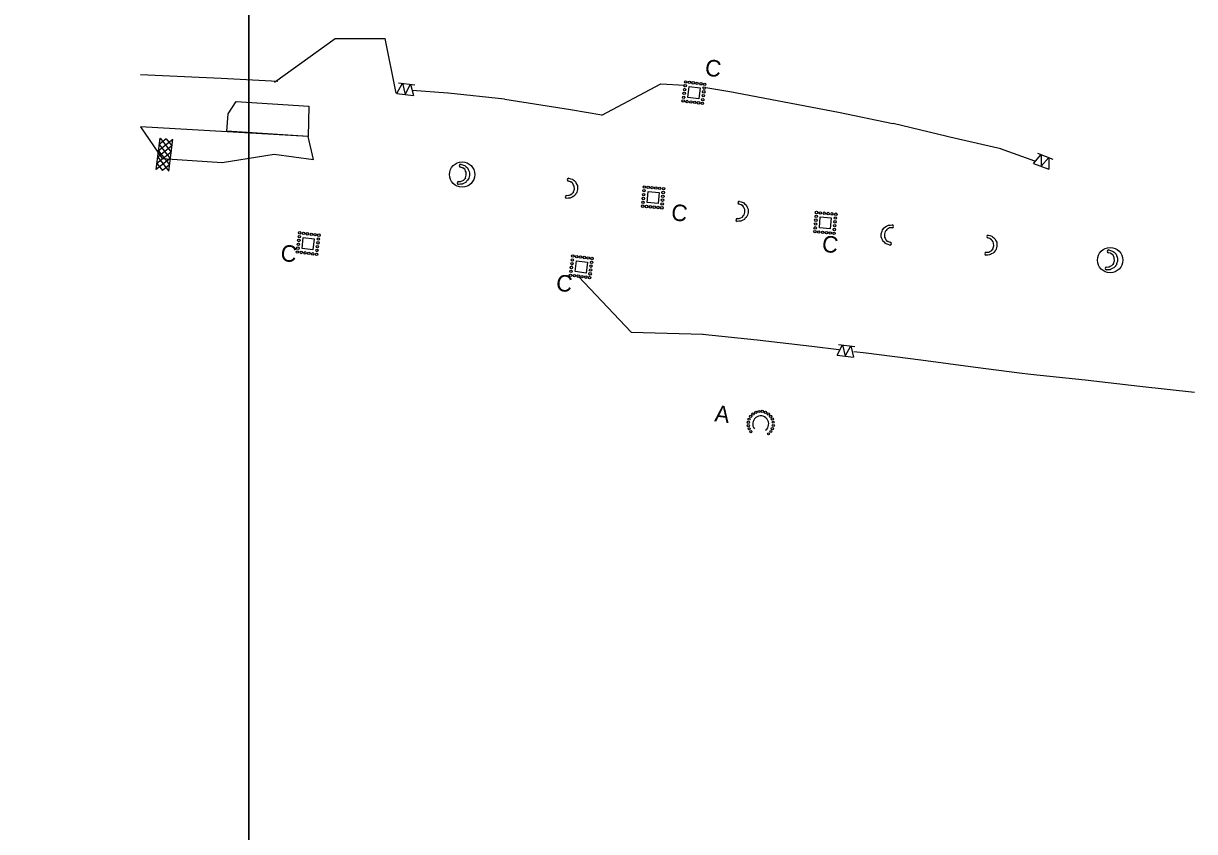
# Model space of a CAD drawing. Extents: x 2470000 to 2520000, y 340000 to 380000.
# Drawn here: x 2479795 to 2480859, y 365742 to 366476 of the extents above; entities that cross this region are included whole.
import ezdxf

# ---------------------------------------------------------------- set-up
doc = ezdxf.new("R2010")
doc.units = 0
for name, color, linetype in [('Bare Soil (Coastal) Drainage Area Border FG Drainage', 7, 'Continuous'), ('Coir Fiber Wattle with PAM Both CELL', 7, 'Continuous'), ('Coir Fiber Wattle with PAM CG CELL', 7, 'Continuous'), ('Label A Both CELL', 7, 'Continuous'), ('Prop Guardrail Anchor Unit CELL', 7, 'Continuous'), ('Prop Structure Anchor Unit CELL', 7, 'Continuous'), ('Rock Pipe Inlet Sediment Trap Type A Both CELL', 7, 'Continuous'), ('Rock Silt Check Type A Both CELL', 7, 'Continuous'), ('Scratch_Level_6', 7, 'Continuous'), ('Sheet Data Field CELL', 7, 'Continuous'), ('Special Sediment Control Fence Section Both CELL', 7, 'Continuous'), ('Wattle Both CELL', 7, 'Continuous'), ('Wattle CG CELL', 7, 'Continuous'), ('Wattle Final CELL', 7, 'Continuous')]:
    doc.layers.add(name, color=color, linetype=linetype)

# ---------------------------------------------------------------- blocks, each defined once
blk = doc.blocks.new('C2')
at = {"layer": 'Prop Guardrail Anchor Unit CELL'}
blk.add_text('C', height=0.3, dxfattribs=at).set_placement((-0.161, -0.136))
blk = doc.blocks.new('A2')
at = {"layer": 'Label A Both CELL'}
blk.add_text('A', height=0.3, dxfattribs=at).set_placement((-0.133, -0.151))

msp = doc.modelspace()

# ---------------------------------------------------------------- linework, layer by layer
at = {"layer": 'Bare Soil (Coastal) Drainage Area Border FG Drainage'}
for points in [[(2479981.3, 366393.9), (2479988.7, 366404.9), (2480054.6, 366400.8), (2480054, 366373.2), (2479980, 366378)], [(2479901.7, 366382), (2479921.4, 366353.2), (2479976, 366349.6), (2480023, 366357.3), (2480058.9, 366352.5), (2480054, 366373.2)]]:
    msp.add_lwpolyline(points, close=True, dxfattribs=at)
at = {"layer": 'Coir Fiber Wattle with PAM Both CELL'}
for p, q in [((2480194.1, 366344.9), (2480192.4, 366345.4)), ((2480194.1, 366344.9), (2480194.5, 366344.8)), ((2480195.6, 366343.8), (2480194.5, 366344.8)), ((2480196.4, 366343.2), (2480195.6, 366343.8)), ((2480197, 366341.9), (2480196.4, 366343.2)), ((2480196.8, 366335.7), (2480197.6, 366338.2)), ((2480197.5, 366340.8), (2480197, 366341.9)), ((2480197.6, 366338.2), (2480197.5, 366340.8)), ((2480197.6, 366338.2), (2480197.6, 366338.2)), ((2480190.6, 366332.5), (2480192.2, 366332.5)), ((2480192.2, 366332.5), (2480193, 366332.6)), ((2480193, 366332.6), (2480193.9, 366333.1)), ((2480193.9, 366333.1), (2480195.2, 366333.7)), ((2480195.4, 366333.9), (2480195.2, 366333.7)), ((2480195.4, 366333.9), (2480196.1, 366334.8)), ((2480196.8, 366335.7), (2480196.1, 366334.8))]:
    msp.add_line(p, q, dxfattribs=at)
msp.add_lwpolyline([(2480192.7, 366348), (2480194.2, 366347.6), (2480195.9, 366347), (2480196.6, 366346.5), (2480197.3, 366345.9), (2480198.7, 366344.7), (2480198.7, 366344.7), (2480198.9, 366344.3), (2480199, 366344.2), (2480199.4, 366343.4), (2480199.7, 366342.8), (2480200.3, 366341.5), (2480200.4, 366340.4), (2480200.6, 366337.9), (2480200.6, 366337.9), (2480199.8, 366335.3), (2480199.4, 366334.4), (2480198.7, 366333.5), (2480198.5, 366333.3), (2480197.9, 366332.6), (2480197.5, 366332), (2480197.3, 366331.9), (2480197.1, 366331.6), (2480197.1, 366331.6), (2480195.7, 366331), (2480194.5, 366330.4), (2480193.8, 366330), (2480192, 366329.9), (2480190.5, 366329.8)], dxfattribs=at)
msp.add_circle((2480193.8, 366338.7), 11.5, dxfattribs=at)
for centre, radius, start in [((2480192.5, 366346.7), 1.3, 83.0023), ((2480190.7, 366331.1), 1.33, 91.8897)]:
    msp.add_arc(centre, radius, start, 263.0023, dxfattribs=at)
at = {"layer": 'Coir Fiber Wattle with PAM CG CELL'}
for p, q in [((2480782.5, 366267.2), (2480780.8, 366267.7)), ((2480782.5, 366267.2), (2480782.8, 366267.1)), ((2480784, 366266.1), (2480782.8, 366267.1)), ((2480784.8, 366265.5), (2480784, 366266.1)), ((2480785.4, 366264.1), (2480784.8, 366265.5)), ((2480785.9, 366263.1), (2480785.4, 366264.1)), ((2480786, 366260.5), (2480785.9, 366263.1)), ((2480779, 366254.7), (2480780.6, 366254.8)), ((2480780.6, 366254.8), (2480781.3, 366254.9)), ((2480781.3, 366254.9), (2480782.3, 366255.4)), ((2480782.3, 366255.4), (2480783.6, 366256)), ((2480783.8, 366256.2), (2480783.6, 366256)), ((2480783.8, 366256.2), (2480784.5, 366257.1)), ((2480785.2, 366258), (2480784.5, 366257.1)), ((2480785.2, 366258), (2480786, 366260.5)), ((2480786, 366260.5), (2480786, 366260.5))]:
    msp.add_line(p, q, dxfattribs=at)
msp.add_lwpolyline([(2480781.1, 366270.3), (2480782.6, 366269.9), (2480784.3, 366269.3), (2480784.9, 366268.8), (2480785.7, 366268.2), (2480787.1, 366267), (2480787.1, 366267), (2480787.3, 366266.6), (2480787.4, 366266.5), (2480787.8, 366265.7), (2480788.1, 366265.1), (2480788.7, 366263.7), (2480788.8, 366262.7), (2480788.9, 366260.2), (2480788.9, 366260.1), (2480788.1, 366257.6), (2480787.8, 366256.7), (2480787.1, 366255.8), (2480786.9, 366255.6), (2480786.3, 366254.9), (2480785.8, 366254.3), (2480785.7, 366254.2), (2480785.5, 366253.9), (2480785.5, 366253.9), (2480784.1, 366253.3), (2480782.9, 366252.7), (2480782.2, 366252.3), (2480780.4, 366252.2), (2480778.9, 366252.1)], dxfattribs=at)
msp.add_circle((2480782.2, 366261), 11.5, dxfattribs=at)
for centre, radius, start in [((2480780.9, 366269), 1.3, 83.0023), ((2480779, 366253.4), 1.33, 91.8897)]:
    msp.add_arc(centre, radius, start, 263.0023, dxfattribs=at)
at = {"layer": 'Prop Structure Anchor Unit CELL'}
for points in [[(2480400, 366418.6), (2480409.9, 366417.4), (2480408.7, 366407.5), (2480398.7, 366408.7)], [(2480362.6, 366323.4), (2480372.6, 366322.5), (2480371.7, 366312.5), (2480361.8, 366313.4)], [(2480519, 366300.2), (2480529, 366299.3), (2480528.1, 366289.3), (2480518.2, 366290.2)], [(2480049.6, 366281.6), (2480059.5, 366280.4), (2480058.3, 366270.5), (2480048.4, 366271.7)], [(2480297.6, 366260.5), (2480307.5, 366259.3), (2480306.3, 366249.3), (2480296.4, 366250.6)]]:
    msp.add_lwpolyline(points, close=True, dxfattribs=at)
for centre in [(2480396.7, 366422.8), (2480400.2, 366422.4), (2480403.6, 366422), (2480407.1, 366421.6), (2480395.4, 366412.4), (2480395.8, 366415.9), (2480396.3, 366419.4), (2480410.6, 366421.1), (2480413.2, 366413.8), (2480413.6, 366417.2), (2480414.1, 366420.7), (2480394.5, 366405.5), (2480395, 366408.9), (2480398, 366405), (2480401.5, 366404.6), (2480405, 366404.2), (2480408.4, 366403.8), (2480411.9, 366403.3), (2480412.3, 366406.8), (2480412.8, 366410.3), (2480359.2, 366327.4), (2480362.7, 366327.1), (2480366.2, 366326.8), (2480369.7, 366326.5), (2480373.2, 366326.2), (2480376.7, 366325.9), (2480358.3, 366317), (2480358.6, 366320.5), (2480358.9, 366324), (2480375.7, 366315.5), (2480376, 366318.9), (2480376.3, 366322.4), (2480357.7, 366310), (2480358, 366313.5), (2480361.2, 366309.7), (2480364.7, 366309.4), (2480368.2, 366309.1), (2480371.6, 366308.8), (2480375.1, 366308.5), (2480375.4, 366312), (2480514.7, 366293.8), (2480515, 366297.3), (2480515.3, 366300.8), (2480515.6, 366304.3), (2480519.1, 366303.9), (2480522.6, 366303.6), (2480526.1, 366303.3), (2480529.6, 366303), (2480532.4, 366295.8), (2480532.7, 366299.2), (2480533.1, 366302.7), (2480046.3, 366285.8), (2480049.8, 366285.4), (2480053.3, 366284.9), (2480056.8, 366284.5), (2480060.2, 366284.1), (2480063.7, 366283.7), (2480514.1, 366286.8), (2480514.4, 366290.3), (2480517.6, 366286.5), (2480521.1, 366286.2), (2480524.6, 366285.9), (2480528, 366285.6), (2480531.5, 366285.3), (2480531.8, 366288.8), (2480532.1, 366292.3), (2480045.1, 366275.4), (2480045.5, 366278.9), (2480045.9, 366282.3), (2480062.4, 366273.2), (2480062.9, 366276.7), (2480063.3, 366280.2), (2480044.2, 366268.4), (2480044.6, 366271.9), (2480047.7, 366268), (2480051.2, 366267.6), (2480054.6, 366267.2), (2480058.1, 366266.7), (2480061.6, 366266.3), (2480062, 366269.8), (2480294.3, 366264.7), (2480297.8, 366264.2), (2480301.3, 366263.8), (2480304.7, 366263.4), (2480308.2, 366263), (2480311.7, 366262.5), (2480293, 366254.3), (2480293.5, 366257.7), (2480293.9, 366261.2), (2480310.4, 366252.1), (2480310.8, 366255.6), (2480311.3, 366259.1), (2480292.2, 366247.3), (2480292.6, 366250.8), (2480295.7, 366246.9), (2480299.1, 366246.5), (2480302.6, 366246), (2480306.1, 366245.6), (2480309.5, 366245.2), (2480310, 366248.6)]:
    msp.add_circle(centre, 1.12, dxfattribs=at)
at = {"layer": 'Rock Pipe Inlet Sediment Trap Type A Both CELL'}
for centre in [(2480453.6, 366113.7), (2480454.3, 366116.6), (2480455.8, 366119.2), (2480457.9, 366121.3), (2480460.5, 366122.8), (2480463.3, 366123.6), (2480466.3, 366123.7), (2480469.2, 366122.9), (2480471.8, 366121.4), (2480473.9, 366119.3), (2480475.4, 366116.8), (2480476.2, 366113.9), (2480453.6, 366110.7), (2480454.4, 366107.9), (2480455.9, 366105.3), (2480472, 366103.3), (2480474.1, 366105.4), (2480475.5, 366108), (2480476.3, 366110.9)]:
    msp.add_circle(centre, 1.01, dxfattribs=at)
msp.add_arc((2480464.9, 366112.3), 7.26, 308.0018, 217.9929, dxfattribs=at)
at = {"layer": 'Rock Silt Check Type A Both CELL'}
for p, q in [((2479916, 366343.2), (2479919.5, 366371.9)), ((2479931, 366370.5), (2479918.1, 366360.4)), ((2479925.2, 366371.2), (2479918.8, 366366.1)), ((2479919.5, 366371.9), (2479929.5, 366359)), ((2479925.2, 366371.2), (2479930.3, 366364.7)), ((2479927.4, 366341.8), (2479931, 366370.5)), ((2479929.5, 366359), (2479916.7, 366348.9)), ((2479930.3, 366364.7), (2479917.4, 366354.6)), ((2479918.1, 366360.4), (2479928.1, 366347.5)), ((2479918.8, 366366.1), (2479928.8, 366353.2)), ((2479928.8, 366353.2), (2479916, 366343.2)), ((2479916.7, 366348.8), (2479921.7, 366342.5)), ((2479917.4, 366354.6), (2479927.4, 366341.8)), ((2479928.1, 366347.5), (2479921.7, 366342.5))]:
    msp.add_line(p, q, dxfattribs=at)
at = {"layer": 'Scratch_Level_6'}
for points in [[(2470000, 360000), (2480000, 360000), (2480000, 370000), (2470000, 370000)], [(2480000, 360000), (2490000, 360000), (2490000, 370000), (2480000, 370000)]]:
    msp.add_lwpolyline(points, close=True, dxfattribs=at)
at = {"layer": 'Sheet Data Field CELL'}
for p, q in [((2480023.3, 366422.5), (2480078.6, 366462.3)), ((2480078.6, 366462.3), (2480124, 366462.2)), ((2480134, 366412.7), (2480124, 366462.2)), ((2479901.8, 366429.7), (2479975, 366426.3)), ((2479975, 366426.3), (2480026.5, 366423.4)), ((2480180.9, 366412.5), (2480148.5, 366415.1)), ((2480232.3, 366407.1), (2480181, 366412.5)), ((2480320.6, 366392.7), (2480374.1, 366421.1)), ((2480374.1, 366421.1), (2480395.6, 366419.9)), ((2480415, 366417.7), (2480436.9, 366414.2)), ((2480436.9, 366414.2), (2480486.2, 366404.8)), ((2480292.1, 366397.4), (2480232.6, 366407)), ((2480486.2, 366404.8), (2480535.4, 366395.3)), ((2480320.6, 366392.7), (2480292.1, 366397.4)), ((2480535.6, 366395.3), (2480584.8, 366385.1)), ((2480634.1, 366373.3), (2480585.1, 366385.1)), ((2480683, 366362), (2480634, 366373.3)), ((2480713.7, 366351), (2480682.7, 366362.1)), ((2480299.4, 366246.1), (2480347.4, 366195.7)), ((2480347.4, 366195.7), (2480412.7, 366193.7)), ((2480411.9, 366193.8), (2480461.7, 366188.6)), ((2480461.6, 366188.6), (2480511.2, 366182.8)), ((2480511.2, 366182.8), (2480535.8, 366179.8)), ((2480549.6, 366178.1), (2480560.8, 366176.8)), ((2480560.7, 366176.8), (2480610.3, 366170.4)), ((2480610.3, 366170.4), (2480659.9, 366163.9)), ((2480659.9, 366163.9), (2480699.9, 366158.7)), ((2480700, 366158.7), (2480709.8, 366157.6)), ((2480709.8, 366157.6), (2480759.4, 366152.2)), ((2480759.4, 366152.2), (2480809.1, 366146.7)), ((2480809.1, 366146.7), (2480858.8, 366141.2))]:
    msp.add_line(p, q, dxfattribs=at)
at = {"layer": 'Special Sediment Control Fence Section Both CELL'}
for p, q in [((2480134.6, 366412.2), (2480149.5, 366410.4)), ((2480135.9, 366422.1), (2480150.7, 366420.3)), ((2480712.5, 366348.8), (2480726.6, 366343.5)), ((2480716.1, 366358.2), (2480730.1, 366352.8)), ((2480535.4, 366184.5), (2480550.3, 366182.7)), ((2480534.2, 366174.6), (2480549.1, 366172.8))]:
    msp.add_line(p, q, dxfattribs=at)
for points in [[(2480134.6, 366412.2), (2480139.6, 366421.7), (2480142.1, 366411.3)], [(2480142.1, 366411.3), (2480147, 366420.7), (2480149.5, 366410.4)], [(2480712.5, 366348.8), (2480719.6, 366356.8), (2480719.6, 366346.2)], [(2480719.6, 366346.2), (2480726.6, 366354.2), (2480726.6, 366343.5)], [(2480534.2, 366174.6), (2480539.1, 366184.1), (2480541.6, 366173.7)], [(2480541.6, 366173.7), (2480546.6, 366183.1), (2480549.1, 366172.8)]]:
    msp.add_lwpolyline(points, dxfattribs=at)
at = {"layer": 'Wattle Both CELL'}
for p, q in [((2480292.2, 366332.2), (2480290.4, 366332.8)), ((2480292.2, 366332.2), (2480292.5, 366332.1)), ((2480293.6, 366331.2), (2480292.5, 366332.1)), ((2480294.4, 366330.5), (2480293.6, 366331.2)), ((2480295, 366329.2), (2480294.4, 366330.5)), ((2480295.5, 366328.1), (2480295, 366329.2)), ((2480295.7, 366325.6), (2480295.5, 366328.1)), ((2480288.7, 366319.8), (2480290.3, 366319.9)), ((2480290.3, 366319.9), (2480291.1, 366319.9)), ((2480291.1, 366319.9), (2480292, 366320.4)), ((2480292, 366320.4), (2480293.3, 366321.1)), ((2480293.5, 366321.3), (2480293.3, 366321.1)), ((2480293.5, 366321.3), (2480294.2, 366322.1)), ((2480294.9, 366323.1), (2480294.2, 366322.1)), ((2480294.9, 366323.1), (2480295.7, 366325.6)), ((2480295.7, 366325.6), (2480295.7, 366325.6)), ((2480447.1, 366311.3), (2480445.4, 366311.8)), ((2480447.1, 366311.3), (2480447.5, 366311.2)), ((2480448.6, 366310.2), (2480447.5, 366311.2)), ((2480449.4, 366309.5), (2480448.6, 366310.2)), ((2480450, 366308.2), (2480449.4, 366309.5)), ((2480450.5, 366307.1), (2480450, 366308.2)), ((2480450.6, 366304.6), (2480450.5, 366307.1)), ((2480443.6, 366298.8), (2480445.2, 366298.9)), ((2480445.2, 366298.9), (2480446, 366299)), ((2480446, 366299), (2480447, 366299.5)), ((2480447, 366299.5), (2480448.3, 366300.1)), ((2480448.4, 366300.3), (2480448.3, 366300.1)), ((2480448.4, 366300.3), (2480449.1, 366301.1)), ((2480449.8, 366302.1), (2480449.1, 366301.1)), ((2480449.8, 366302.1), (2480450.6, 366304.6)), ((2480450.6, 366304.6), (2480450.6, 366304.6))]:
    msp.add_line(p, q, dxfattribs=at)
for points in [[(2480290.7, 366335.4), (2480292.2, 366334.9), (2480293.9, 366334.4), (2480294.6, 366333.9), (2480295.4, 366333.2), (2480296.8, 366332.1), (2480296.8, 366332.1), (2480297, 366331.7), (2480297, 366331.6), (2480297.4, 366330.7), (2480297.7, 366330.1), (2480298.4, 366328.8), (2480298.5, 366327.8), (2480298.6, 366325.2), (2480298.6, 366325.2), (2480297.8, 366322.7), (2480297.5, 366321.7), (2480296.8, 366320.9), (2480296.6, 366320.7), (2480296, 366320), (2480295.5, 366319.4), (2480295.4, 366319.3), (2480295.2, 366319), (2480295.2, 366319), (2480293.8, 366318.3), (2480292.6, 366317.7), (2480291.9, 366317.4), (2480290.1, 366317.2), (2480288.6, 366317.1)], [(2480445.7, 366314.4), (2480447.2, 366313.9), (2480448.9, 366313.4), (2480449.6, 366312.9), (2480450.3, 366312.2), (2480451.7, 366311.1), (2480451.7, 366311.1), (2480451.9, 366310.7), (2480452, 366310.6), (2480452.4, 366309.7), (2480452.7, 366309.1), (2480453.3, 366307.8), (2480453.4, 366306.8), (2480453.6, 366304.2), (2480453.6, 366304.2), (2480452.8, 366301.7), (2480452.4, 366300.7), (2480451.7, 366299.9), (2480451.6, 366299.7), (2480450.9, 366299), (2480450.5, 366298.4), (2480450.3, 366298.3), (2480450.1, 366298), (2480450.1, 366298), (2480448.7, 366297.3), (2480447.5, 366296.8), (2480446.8, 366296.4), (2480445.1, 366296.3), (2480443.5, 366296.2)]]:
    msp.add_lwpolyline(points, dxfattribs=at)
for centre, radius, start, end in [((2480290.6, 366334.1), 1.3, 83.2609, 263.2609), ((2480288.8, 366318.5), 1.33, 92.1483, 263.2609), ((2480445.5, 366313.1), 1.3, 83.0023, 263.0023), ((2480443.7, 366297.5), 1.33, 91.8897, 263.0023)]:
    msp.add_arc(centre, radius, start, end, dxfattribs=at)
at = {"layer": 'Wattle CG CELL'}
for p, q in [((2480673, 366280.6), (2480671.2, 366281.2)), ((2480673, 366280.6), (2480673.3, 366280.5)), ((2480674.4, 366279.5), (2480673.3, 366280.5)), ((2480675.2, 366278.9), (2480674.4, 366279.5)), ((2480675.9, 366277.6), (2480675.2, 366278.9)), ((2480675.7, 366271.4), (2480676.5, 366273.9)), ((2480676.4, 366276.5), (2480675.9, 366277.6)), ((2480676.5, 366274), (2480676.4, 366276.5)), ((2480676.5, 366274), (2480676.5, 366273.9)), ((2480669.5, 366268.2), (2480671.1, 366268.2)), ((2480671.1, 366268.2), (2480671.9, 366268.3)), ((2480671.9, 366268.3), (2480672.8, 366268.8)), ((2480672.8, 366268.8), (2480674.1, 366269.4)), ((2480674.3, 366269.6), (2480674.1, 366269.4)), ((2480674.3, 366269.6), (2480675, 366270.5)), ((2480675.7, 366271.4), (2480675, 366270.5))]:
    msp.add_line(p, q, dxfattribs=at)
msp.add_lwpolyline([(2480671.5, 366283.7), (2480673, 366283.3), (2480674.8, 366282.8), (2480675.4, 366282.2), (2480676.2, 366281.6), (2480677.6, 366280.5), (2480677.6, 366280.4), (2480677.8, 366280), (2480677.8, 366280), (2480678.2, 366279.1), (2480678.5, 366278.5), (2480679.2, 366277.2), (2480679.3, 366276.2), (2480679.4, 366273.6), (2480679.4, 366273.6), (2480678.6, 366271.1), (2480678.3, 366270.1), (2480677.6, 366269.2), (2480677.5, 366269.1), (2480676.8, 366268.3), (2480676.4, 366267.8), (2480676.2, 366267.6), (2480676, 366267.4), (2480676, 366267.3), (2480674.6, 366266.7), (2480673.4, 366266.1), (2480672.7, 366265.7), (2480671, 366265.6), (2480669.4, 366265.5)], dxfattribs=at)
for centre, radius, start in [((2480671.4, 366282.4), 1.3, 83.2609), ((2480669.6, 366266.8), 1.33, 92.1483)]:
    msp.add_arc(centre, radius, start, 263.2609, dxfattribs=at)
at = {"layer": 'Wattle Final CELL'}
for p, q in [((2480578, 366287.1), (2480577.2, 366284.5)), ((2480577.2, 366284.5), (2480577.2, 366284.5)), ((2480577.2, 366284.5), (2480577.3, 366282)), ((2480578, 366287.1), (2480578.7, 366288)), ((2480579.4, 366288.8), (2480578.7, 366288)), ((2480579.4, 366288.8), (2480579.6, 366289)), ((2480580.9, 366289.7), (2480579.6, 366289)), ((2480581.9, 366290.2), (2480580.9, 366289.7)), ((2480582.7, 366290.2), (2480581.9, 366290.2)), ((2480584.2, 366290.3), (2480582.7, 366290.2)), ((2480577.3, 366282), (2480577.8, 366280.9)), ((2480577.8, 366280.9), (2480578.5, 366279.6)), ((2480578.5, 366279.6), (2480579.2, 366278.9)), ((2480579.2, 366278.9), (2480580.4, 366278)), ((2480580.7, 366277.9), (2480580.4, 366278)), ((2480580.7, 366277.9), (2480582.5, 366277.3))]:
    msp.add_line(p, q, dxfattribs=at)
msp.add_lwpolyline([(2480582.1, 366274.7), (2480580.7, 366275.2), (2480578.9, 366275.7), (2480578.3, 366276.2), (2480577.5, 366276.9), (2480576.1, 366278), (2480576.1, 366278.1), (2480575.9, 366278.5), (2480575.9, 366278.5), (2480575.4, 366279.4), (2480575.2, 366280), (2480574.5, 366281.3), (2480574.4, 366282.3), (2480574.3, 366284.9), (2480574.3, 366284.9), (2480575.1, 366287.4), (2480575.4, 366288.4), (2480576.1, 366289.3), (2480576.3, 366289.4), (2480576.9, 366290.2), (2480577.4, 366290.7), (2480577.5, 366290.8), (2480577.7, 366291.1), (2480577.7, 366291.1), (2480579.1, 366291.8), (2480580.3, 366292.4), (2480581, 366292.7), (2480582.8, 366292.8), (2480584.3, 366293)], dxfattribs=at)
for centre, radius, start in [((2480584.2, 366291.6), 1.33, 271.8897), ((2480582.3, 366276), 1.3, 263.0023)]:
    msp.add_arc(centre, radius, start, 83.0023, dxfattribs=at)

# ---------------------------------------------------------------- block references
at = {"layer": 'Prop Structure Anchor Unit CELL'}
for p, xscale, yscale, rotation in [((2480422.5, 366434.5), 49.99999999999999, 50.00000000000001, -6.997703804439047), ((2480391.8, 366303.2), 50.00000000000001, 49.99999999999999, -6.997703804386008), ((2480037.1, 366266.3), 50.00000000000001, 49.99999999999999, -6.997703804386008), ((2480528.7, 366274.6), 50.00000000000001, 49.99999999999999, -6.997703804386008), ((2480287.3, 366239.2), 50.00000000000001, 49.99999999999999, -6.997703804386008)]:
    msp.add_blockref('C2', p, dxfattribs=dict(at, xscale=xscale, yscale=yscale, rotation=rotation))
at = {"layer": 'Rock Pipe Inlet Sediment Trap Type A Both CELL', "xscale": 50.00000000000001, "yscale": 49.99999999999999, "rotation": -6.997703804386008}
msp.add_blockref('A2', (2480430, 366121.4), dxfattribs=at)

doc.saveas('drawing.dxf')
